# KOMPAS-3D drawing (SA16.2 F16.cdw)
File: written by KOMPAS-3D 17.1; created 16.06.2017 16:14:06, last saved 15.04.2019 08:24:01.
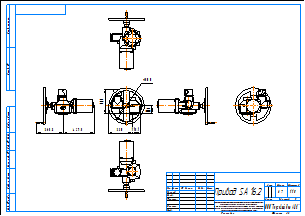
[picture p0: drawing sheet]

Sheet 1: A3, landscape

Title block, sheet 1: name: Привод SA 16.2; material: Сталь 20  ГОСТ 1050-2013; mass: 67; sheets: 1; sheet format: A3; stored path: C:\Users\kka\KOMPAS_Work\!Trash\Электроприводы\SA 16.2 F16.cdw

Views: Спереди 1, Проекционный вид 2, Проекционный вид 3, Проекционный вид 4, Проекционный вид 5, Проекционный вид 6
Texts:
  Klimkovich
  ADL
  Рама для чертежей
  Лит-Масса-Масштаб
  Материал-Предприятие
  Масштаб
  Изм.
  Лист
  № докум.
  Подп.
  Дата
  Лит.
  Разраб.
  Пров.
  Т.контр.
  Листов
  Внимание! Данный продукт является объектом авторского права ООО «Торговый Дом АДЛ».
  Запрещается изменение, копирование, распространение
  (в том числе путем копирования на другие сайты и ресурсы в Интернете)
  или любое иное использование информации и объектов без предварительного
  согласия правообладателя (ООО «Торговый Дом АДЛ»).
  Н.контр.
  Утв.
  ООО "Торговый дом АДЛ"
  Изменение
  Номер документа
  Подпись
  Обозначение документа
  Наименование изделия
  Масса изделия по ГОСТ 2.109-73
  Порядковый номер листа
  Общее количество листов в документе
  Характер работы, выполненной лицом, подписавшим документ
  Наименование или индекс предприятия, выпускающего документ
  Инв. № подл.
  Подп. и дата
  Взам. инв. №
  Инв. № дубл.
  Инвентарный номер подлинника по ГОСТ 2.501-68
  Подпись принявшего подлинник в отдел технической документации
  Инвентарный номер подлинника, взамен которого выпущен данный подлинник
  Инвентарный номер дубликата по ГОСТ 2.502-68
  Подпись принявшего дубликат в отдел технической документации
  Справ. №
  Перв. примен.
  Обозначение документа, взамен или на основании которого выпущен данный документ
  Обозначение документа, в котором впервые записан данный документ
  Подпись лица, копировавшего чертеж
  Обозначение формата листа
  !Рама для чертежа
Dimensions and other numbers on the sheet: 500; 340; 115,1; 330; 110; 429,5; 365,8; 1:10; 1; 67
